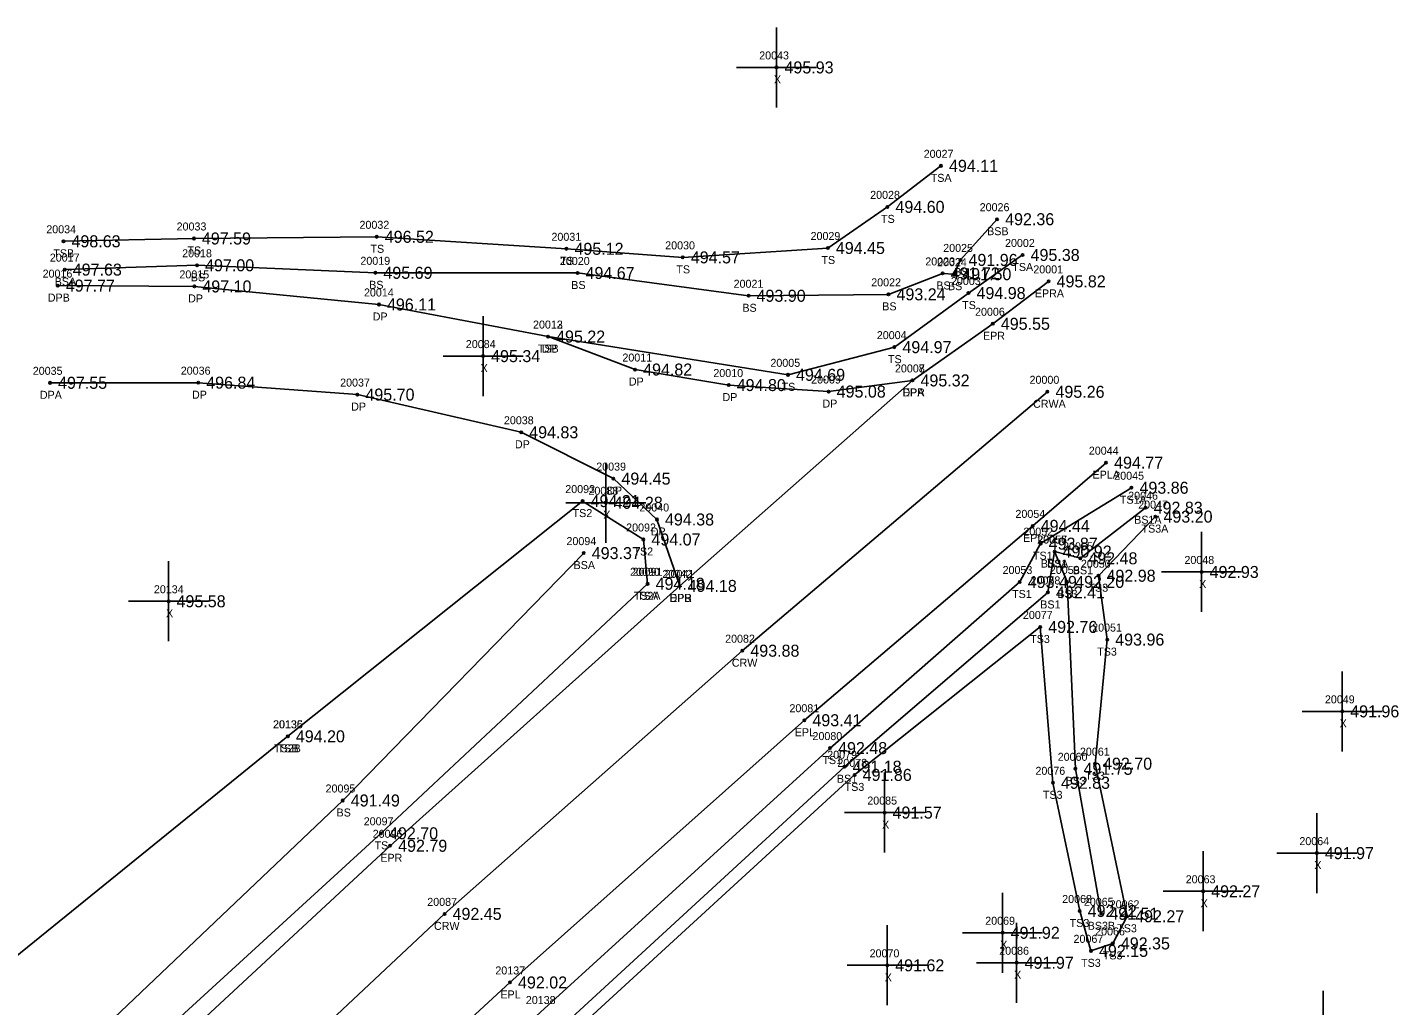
# Model space of a CAD drawing. Extents: x 1741010 to 1742139, y 749382 to 750625.
# Drawn here: x 1741967.6 to 1742139, y 750502.8 to 750625 of the extents above; entities that cross this region are included whole.
import ezdxf

# ---------------------------------------------------------------- set-up
doc = ezdxf.new("R2010")
doc.units = 0
for name, color, linetype in [('RD_DTM_BkLn1', 7, 'Continuous'), ('RD_DTM_BkLn2', 7, 'Continuous'), ('RD_DTM_BkLn_txCode', 7, 'Continuous'), ('RD_EX_Driveway', 7, 'Continuous'), ('RD_EX_Driveway_txCode', 7, 'Continuous'), ('RD_EX_Misc', 7, 'Continuous'), ('RD_EX_Misc_txCode', 7, 'Continuous'), ('RD_EX_Road', 7, 'Continuous'), ('RD_EX_Road_txCode', 7, 'Continuous'), ('RD_EX_TX_Driveway_ELEV', 7, 'Continuous'), ('RD_EX_TX_Misc_ELEV', 7, 'Continuous'), ('RD_EX_TX_Road_ELEV', 7, 'Continuous'), ('RD_HC_Survey_ELEV', 7, 'Continuous'), ('RD_HC_Survey_txCode', 7, 'Continuous'), ('RD_SMD_Locator', 7, 'Continuous')]:
    doc.layers.add(name, color=color, linetype=linetype)

msp = doc.modelspace()

# ---------------------------------------------------------------- linework, layer by layer
at = {"layer": 'RD_DTM_BkLn1'}
msp.add_lwpolyline([(1742095.1, 750579.47), (1742056.96, 750547.11), (1742019.74, 750514.22), (1741983.45, 750480.17), (1741948.01, 750445.01), (1741913.15, 750409.3), (1741879.03, 750372.99), (1741811.59, 750300.09), (1741743.65, 750226.52), (1741676.29, 750153.06), (1741642.32, 750115.53), (1741610.32, 750077.63)], dxfattribs=at)
at = {"layer": 'RD_DTM_BkLn2'}
for points in [[(1742081.79, 750607.71), (1742075.1, 750602.58), (1742067.65, 750597.44), (1742049.52, 750596.27), (1742034.98, 750597.34), (1742011.27, 750598.84), (1741988.41, 750598.63), (1741972.11, 750598.28)], [(1741972.27, 750594.74), (1741988.81, 750595.28), (1742011.1, 750594.34), (1742036.36, 750594.32), (1742057.74, 750591.47), (1742075.23, 750591.65), (1742081.99, 750594.26), (1742083.45, 750594.17), (1742084.23, 750595.95), (1742088.81, 750601.04)], [(1742091.99, 750596.57), (1742085.23, 750591.81), (1742075.97, 750585.05), (1742062.67, 750581.59), (1742032.68, 750586.37)], [(1742105.6, 750567.48), (1742094.25, 750560.49), (1742091.64, 750555.7), (1742067.93, 750534.94), (1742031.73, 750501.95), (1741994.85, 750467.63), (1741959.82, 750432.06), (1741925.8, 750396.31), (1741891.25, 750362.62), (1741824.36, 750287.7), (1741756.44, 750214.6), (1741688.69, 750142.04), (1741655.55, 750103.43), (1741644.64, 750083.31), (1741626.06, 750060.3), (1741620, 750055.3), (1741614.97, 750059.12), (1741617.5, 750064.27), (1741619.23, 750067.96)], [(1742107.37, 750564.98), (1742099.21, 750558.66), (1742095.99, 750559.5), (1742095.15, 750554.39), (1742069.73, 750532.61), (1742034.06, 750499.81), (1741997.6, 750464.99), (1741961.88, 750429.54), (1741928.13, 750394.17), (1741895.34, 750359.02), (1741826.5, 750286.36), (1741758.73, 750213.29), (1741690.1, 750140.59), (1741658.36, 750099.77), (1741650.43, 750077.87), (1741632.9, 750061.59), (1741621.97, 750051.56), (1741618.99, 750048.78), (1741611.88, 750047.79)], [(1742045.12, 750555.47), (1742044.6, 750561.01), (1742036.99, 750565.81), (1742000.15, 750536.41)], [(1742108.6, 750563.87), (1742101.48, 750556.48), (1742102.57, 750548.5), (1742101.05, 750532.99), (1742105.06, 750513.92), (1742103.27, 750510.53), (1742100.54, 750509.6), (1742099.13, 750514.58), (1742095.78, 750530.6), (1742094.19, 750550.08), (1742071, 750531.59), (1742035.26, 750498.87), (1741998.91, 750463.73), (1741964.71, 750427.12), (1741930.26, 750392.09), (1741896.36, 750357.96), (1741828.15, 750284.74), (1741760.22, 750211.9), (1741691.37, 750138.81), (1741661.95, 750096.11), (1741655.14, 750072.69), (1741637.21, 750056.01), (1741627.61, 750046.43), (1741623.09, 750045.5)], [(1742095.99, 750559.5), (1742097.56, 750555.71), (1742098.6, 750532.35), (1742101.83, 750514.23)], [(1742037.14, 750559.31), (1742007.02, 750528.39), (1741970.04, 750493.22), (1741934.59, 750458.38), (1741921.36, 750445.71), (1741908.08, 750432.71)], [(1742045.12, 750555.47), (1742011.8, 750524.29), (1741973.5, 750489.25), (1741973.31, 750490.05), (1741936.72, 750456.96), (1741909.62, 750428.48), (1741903.95, 750430.57), (1741885.98, 750437.55), (1741892.83, 750449.28), (1741921.95, 750473.14), (1741959.65, 750503.64), (1742000.15, 750536.41)]]:
    msp.add_lwpolyline(points, dxfattribs=at)
at = {"layer": 'RD_EX_Driveway'}
for points in [[(1742078.23, 750580.89), (1742067.75, 750579.5), (1742055.26, 750580.31), (1742043.56, 750582.25), (1742032.68, 750586.37), (1742011.54, 750590.38), (1741988.47, 750592.64), (1741971.4, 750592.74)], [(1741970.43, 750580.59), (1741988.95, 750580.61), (1742008.85, 750579.12), (1742029.32, 750574.41), (1742040.85, 750568.62), (1742046.29, 750563.51), (1742049.13, 750555.21)]]:
    msp.add_lwpolyline(points, dxfattribs=at)
at = {"layer": 'RD_EX_Misc'}
for p, q in [((1742061.23, 750615.01), (1742061.23, 750625.01)), ((1742056.23, 750620.01), (1742066.23, 750620.01)), ((1742024.56, 750578.93), (1742024.56, 750588.93)), ((1742019.56, 750583.93), (1742029.56, 750583.93)), ((1742039.88, 750560.6), (1742039.88, 750570.6)), ((1742034.88, 750565.6), (1742044.88, 750565.6)), ((1742114.37, 750551.95), (1742114.37, 750561.95)), ((1741985.24, 750548.29), (1741985.24, 750558.29)), ((1742109.37, 750556.95), (1742119.37, 750556.95)), ((1741980.24, 750553.29), (1741990.24, 750553.29)), ((1742131.94, 750534.53), (1742131.94, 750544.53)), ((1742126.94, 750539.53), (1742136.94, 750539.53)), ((1742074.74, 750521.88), (1742074.74, 750531.88)), ((1742069.74, 750526.88), (1742079.74, 750526.88)), ((1742128.77, 750516.81), (1742128.77, 750526.81)), ((1742114.56, 750512.04), (1742114.56, 750522.04)), ((1742123.77, 750521.81), (1742133.77, 750521.81)), ((1742089.5, 750506.86), (1742089.5, 750516.86)), ((1742109.56, 750517.04), (1742119.56, 750517.04)), ((1742075.07, 750502.79), (1742075.07, 750512.79)), ((1742084.5, 750511.86), (1742094.5, 750511.86)), ((1742091.25, 750503.11), (1742091.25, 750513.11)), ((1742086.25, 750508.11), (1742096.25, 750508.11)), ((1742070.07, 750507.79), (1742080.07, 750507.79)), ((1742129.55, 750494.61), (1742129.55, 750504.61))]:
    msp.add_line(p, q, dxfattribs=at)
at = {"layer": 'RD_EX_Road'}
for points in [[(1742095.24, 750593.27), (1742088.27, 750587.97), (1742078.23, 750580.89), (1742049.13, 750555.21), (1742012.94, 750522.73), (1741975.54, 750488.03), (1741940.71, 750452.82), (1741916.22, 750428.67), (1741904.72, 750416.99), (1741884.38, 750395.02), (1741870.75, 750380.27), (1741817.36, 750322.98), (1741803.89, 750307.66), (1741783.86, 750287.33), (1741735.44, 750234.07), (1741718.84, 750214.98), (1741710.25, 750205.58), (1741668.97, 750159.8), (1741635, 750122.49), (1741604.35, 750087.7), (1741600.63, 750085.47)], [(1742102.43, 750570.61), (1742093.26, 750562.71), (1742064.72, 750538.42), (1742027.92, 750505.65), (1741991.25, 750471.83), (1741956.32, 750436.98), (1741921.43, 750401.39), (1741886.79, 750364.93), (1741819.64, 750292.67), (1741751.78, 750219.01), (1741684.42, 750145.59), (1741650.98, 750108.5), (1741637.17, 750092.42), (1741621.17, 750073.94), (1741621.31, 750072.22), (1741619.24, 750070.27)]]:
    msp.add_lwpolyline(points, dxfattribs=at)
at = {"layer": 'RD_SMD_Locator'}
for centre in [(1742061.23, 750620.01), (1742081.79, 750607.71), (1742075.1, 750602.58), (1742088.81, 750601.04), (1742011.27, 750598.84), (1741972.11, 750598.28), (1741988.41, 750598.63), (1742034.98, 750597.34), (1742067.65, 750597.44), (1741988.81, 750595.28), (1742049.52, 750596.27), (1742084.23, 750595.95), (1742091.99, 750596.57), (1741972.27, 750594.74), (1742011.1, 750594.34), (1742036.36, 750594.32), (1742081.99, 750594.26), (1742083.45, 750594.17), (1741971.4, 750592.74), (1741988.47, 750592.64), (1742095.24, 750593.27), (1742011.54, 750590.38), (1742057.74, 750591.47), (1742075.23, 750591.65), (1742085.23, 750591.81), (1742088.27, 750587.97), (1742032.68, 750586.37), (1742032.68, 750586.37), (1742075.97, 750585.05), (1742024.56, 750583.93), (1742043.56, 750582.25), (1742062.67, 750581.59), (1741970.43, 750580.59), (1741988.95, 750580.61), (1742055.26, 750580.31), (1742078.23, 750580.89), (1742078.23, 750580.89), (1742008.85, 750579.12), (1742067.75, 750579.5), (1742095.1, 750579.47), (1742029.32, 750574.41), (1742102.43, 750570.61), (1742040.85, 750568.62), (1742105.6, 750567.48), (1742036.99, 750565.81), (1742039.88, 750565.6), (1742107.37, 750564.98), (1742046.29, 750563.51), (1742093.26, 750562.71), (1742108.6, 750563.87), (1742044.6, 750561.01), (1742037.14, 750559.31), (1742094.25, 750560.49), (1742095.99, 750559.5), (1742095.99, 750559.5), (1742099.21, 750558.66), (1742101.48, 750556.48), (1742114.37, 750556.95), (1742045.12, 750555.47), (1742045.12, 750555.47), (1742049.13, 750555.21), (1742049.13, 750555.21), (1742091.64, 750555.7), (1742095.15, 750554.39), (1742097.56, 750555.71), (1741985.24, 750553.29), (1742094.19, 750550.08), (1742102.57, 750548.5), (1742056.96, 750547.11), (1742131.94, 750539.53), (1742064.72, 750538.42), (1742000.15, 750536.41), (1742000.15, 750536.41), (1742067.93, 750534.94), (1742069.73, 750532.61), (1742098.6, 750532.35), (1742101.05, 750532.99), (1742071, 750531.59), (1742095.78, 750530.6), (1742007.02, 750528.39), (1742074.74, 750526.88), (1742011.8, 750524.29), (1742012.94, 750522.73), (1742128.77, 750521.81), (1742114.56, 750517.04), (1742019.74, 750514.22), (1742099.13, 750514.58), (1742101.83, 750514.23), (1742105.06, 750513.92), (1742089.5, 750511.86), (1742100.54, 750509.6), (1742103.27, 750510.53), (1742091.25, 750508.11), (1742075.07, 750507.79), (1742027.92, 750505.65)]:
    msp.add_circle(centre, 0.15, dxfattribs=at)

# ---------------------------------------------------------------- texts
at = {"layer": 'RD_DTM_BkLn_txCode'}
for s, p in [('20027', (1742079.63, 750608.71)), ('TSA', (1742080.51, 750605.71)), ('20028', (1742072.94, 750603.58)), ('20026', (1742086.63, 750602.04)), ('20033', (1741986.25, 750599.63)), ('20032', (1742009.11, 750599.84)), ('TS', (1742074.3, 750600.58)), ('20034', (1741969.96, 750599.28)), ('20031', (1742033.1, 750598.34)), ('20029', (1742065.49, 750598.44)), ('BSB', (1742087.56, 750599.04)), ('TSB', (1741970.84, 750596.28)), ('20018', (1741986.94, 750596.28)), ('TS', (1741987.61, 750596.63)), ('TS', (1742010.48, 750596.84)), ('20030', (1742047.32, 750597.27)), ('20025', (1742082.07, 750596.95)), ('20002', (1742089.8, 750597.57)), ('20017', (1741970.4, 750595.74)), ('20019', (1742009.22, 750595.34)), ('TS', (1742034.18, 750595.34)), ('20020', (1742034.16, 750595.32)), ('TS', (1742066.85, 750595.44)), ('20023', (1742079.83, 750595.26)), ('20024', (1742081.3, 750595.17)), ('TSA', (1742090.71, 750594.57)), ('BSA', (1741971.01, 750592.74)), ('BS', (1741988.03, 750593.28)), ('TS', (1742048.72, 750594.27)), ('20003', (1742083.04, 750592.81)), ('BS', (1742083.45, 750593.95)), ('BS', (1742010.32, 750592.34)), ('BS', (1742035.58, 750592.32)), ('20021', (1742055.87, 750592.47)), ('20022', (1742073.07, 750592.65)), ('BS', (1742081.21, 750592.26)), ('BS', (1742082.67, 750592.17)), ('BS', (1742056.97, 750589.47)), ('BS', (1742074.45, 750589.65)), ('TS', (1742084.44, 750589.81)), ('20013', (1742030.8, 750587.37)), ('20004', (1742073.77, 750586.05)), ('TSB', (1742031.41, 750584.37)), ('20005', (1742060.47, 750582.59)), ('TS', (1742075.17, 750583.05)), ('TS', (1742061.87, 750579.59)), ('20045', (1742103.45, 750568.48)), ('20093', (1742034.83, 750566.81)), ('TS1A', (1742104.15, 750565.48)), ('20046', (1742105.19, 750565.98)), ('TS2', (1742035.75, 750563.81)), ('20047', (1742106.44, 750564.87)), ('20092', (1742042.44, 750562.01)), ('BS1A', (1742105.94, 750562.98)), ('TS3A', (1742106.86, 750561.87)), ('20094', (1742034.98, 750560.31)), ('20052', (1742092.09, 750561.49)), ('20056', (1742093.81, 750560.5)), ('20057', (1742093.84, 750560.5)), ('TS2', (1742043.35, 750559.01)), ('TS1', (1742093.29, 750558.49)), ('20055', (1742097.05, 750559.66)), ('BSA', (1742035.87, 750557.31)), ('20053', (1742089.49, 750556.7)), ('BS3A', (1742094.28, 750557.5)), ('BS1', (1742095.05, 750557.5)), ('20059', (1742095.4, 750556.71)), ('20050', (1742099.28, 750557.48)), ('20090', (1742042.92, 750556.47)), ('20091', (1742043.25, 750556.47)), ('20058', (1742092.99, 750555.39)), ('BS1', (1742098.27, 750556.66)), ('TS2A', (1742043.39, 750553.47)), ('TSA', (1742043.84, 750553.47)), ('TS1', (1742090.68, 750553.7)), ('BS3', (1742096.33, 750553.71)), ('TS3', (1742100.23, 750554.48)), ('BS1', (1742094.2, 750552.39)), ('20077', (1742092.03, 750551.08)), ('20051', (1742100.69, 750549.5)), ('TS3', (1742092.94, 750548.08)), ('TS3', (1742101.32, 750546.5)), ('20136', (1741998.29, 750537.41)), ('20135', (1741998.32, 750537.41)), ('20080', (1742065.73, 750535.94)), ('TS2B', (1741998.43, 750534.41)), ('TSB', (1741998.88, 750534.41)), ('TS1', (1742066.97, 750532.94)), ('20079', (1742067.57, 750533.61)), ('20060', (1742096.38, 750533.35)), ('20061', (1742099.16, 750533.99)), ('20078', (1742068.84, 750532.59)), ('20076', (1742093.6, 750531.6)), ('20095', (1742004.87, 750529.39)), ('BS1', (1742068.78, 750530.61)), ('TS3', (1742069.75, 750529.59)), ('BS3', (1742097.37, 750530.35)), ('TS3', (1742099.81, 750530.99)), ('TS3', (1742094.53, 750528.6)), ('BS', (1742006.24, 750526.39)), ('20097', (1742009.64, 750525.29)), ('TS', (1742011, 750522.29)), ('20068', (1742096.94, 750515.58)), ('20065', (1742099.65, 750515.23)), ('20062', (1742102.88, 750514.92)), ('TS3', (1742097.88, 750512.58)), ('BS3B', (1742100.13, 750512.23)), ('20067', (1742098.36, 750510.6)), ('20066', (1742101.06, 750511.53)), ('TS3', (1742103.82, 750511.92)), ('TS3', (1742099.3, 750507.6)), ('TS3', (1742102.02, 750508.53)), ('20138', (1742029.9, 750502.95))]:
    msp.add_text(s, height=1, dxfattribs=at).set_placement(p)
at = {"layer": 'RD_EX_Driveway_txCode'}
for s, p in [('20016', (1741969.5, 750593.74)), ('20015', (1741986.6, 750593.64)), ('20014', (1742009.67, 750591.38)), ('DPB', (1741970.15, 750590.74)), ('DP', (1741987.69, 750590.64)), ('DP', (1742010.76, 750588.38)), ('20012', (1742030.8, 750587.37)), ('DP', (1742031.9, 750584.37)), ('20011', (1742041.97, 750583.25)), ('20035', (1741968.27, 750581.59)), ('20036', (1741986.77, 750581.61)), ('20010', (1742053.34, 750581.31)), ('20008', (1742076.04, 750581.89)), ('20037', (1742006.69, 750580.12)), ('DP', (1742042.78, 750580.25)), ('20009', (1742065.56, 750580.5)), ('DPA', (1741969.16, 750578.59)), ('DP', (1741988.17, 750578.61)), ('DP', (1742054.48, 750578.31)), ('DP', (1742066.97, 750577.5)), ('DPA', (1742076.97, 750578.89)), ('DP', (1742008.07, 750577.12)), ('20038', (1742027.16, 750575.41)), ('DP', (1742028.54, 750572.41)), ('20039', (1742038.7, 750569.62)), ('DP', (1742040.07, 750566.62)), ('20040', (1742044.09, 750564.51)), ('DP', (1742045.51, 750561.51)), ('20041', (1742047.25, 750556.21)), ('DPB', (1742047.87, 750553.21))]:
    msp.add_text(s, height=1, dxfattribs=at).set_placement(p)
at = {"layer": 'RD_EX_Misc_txCode'}
for s, p in [('20043', (1742059.07, 750621.01)), ('X', (1742060.91, 750618.01)), ('20084', (1742022.4, 750584.93)), ('X', (1742024.25, 750581.93)), ('20083', (1742037.73, 750566.6)), ('X', (1742039.57, 750563.6)), ('20048', (1742112.22, 750557.95)), ('20134', (1741983.41, 750554.29)), ('X', (1742114.06, 750554.95)), ('X', (1741984.93, 750551.29)), ('20049', (1742129.78, 750540.53)), ('X', (1742131.62, 750537.53)), ('20085', (1742072.58, 750527.88)), ('X', (1742074.43, 750524.88)), ('20064', (1742126.59, 750522.81)), ('X', (1742128.46, 750519.81)), ('20063', (1742112.38, 750518.04)), ('X', (1742114.24, 750515.04)), ('20069', (1742087.32, 750512.86)), ('20070', (1742072.87, 750508.79)), ('20086', (1742089.07, 750509.11)), ('X', (1742089.19, 750509.86)), ('X', (1742074.76, 750505.79)), ('X', (1742090.93, 750506.11))]:
    msp.add_text(s, height=1, dxfattribs=at).set_placement(p)
at = {"layer": 'RD_EX_Road_txCode'}
for s, p in [('20001', (1742093.33, 750594.27)), ('EPRA', (1742093.52, 750591.27)), ('20006', (1742086.05, 750588.97)), ('EPR', (1742087.04, 750585.97)), ('20007', (1742076.04, 750581.89)), ('EPR', (1742077.01, 750578.89)), ('20044', (1742100.27, 750571.61)), ('EPLA', (1742100.73, 750568.61)), ('20054', (1742091.1, 750563.71)), ('EPL', (1742092.06, 750560.71)), ('20042', (1742046.97, 750556.21)), ('EPR', (1742047.9, 750553.21)), ('20081', (1742062.85, 750539.42)), ('EPL', (1742063.52, 750536.42)), ('20096', (1742010.76, 750523.73)), ('EPR', (1742011.71, 750520.73)), ('20137', (1742026.09, 750506.65)), ('EPL', (1742026.72, 750503.65))]:
    msp.add_text(s, height=1, dxfattribs=at).set_placement(p)
at = {"layer": 'RD_EX_TX_Driveway_ELEV'}
for s, p in [('497.77', (1741972.4, 750591.99)), ('497.10', (1741989.47, 750591.89)), ('496.11', (1742012.54, 750589.63)), ('495.22', (1742033.68, 750585.62)), ('494.82', (1742044.56, 750581.5)), ('497.55', (1741971.43, 750579.84)), ('496.84', (1741989.95, 750579.86)), ('494.80', (1742056.26, 750579.56)), ('495.08', (1742068.75, 750578.75)), ('495.32', (1742079.23, 750580.14)), ('495.70', (1742009.85, 750578.37)), ('494.83', (1742030.32, 750573.66)), ('494.45', (1742041.85, 750567.87)), ('494.38', (1742047.29, 750562.76)), ('494.18', (1742050.13, 750554.46))]:
    msp.add_text(s, height=1.5, dxfattribs=at).set_placement(p)
at = {"layer": 'RD_EX_TX_Misc_ELEV'}
for s, p in [('495.93', (1742062.23, 750619.26)), ('494.11', (1742082.79, 750606.96)), ('494.60', (1742076.1, 750601.83)), ('492.36', (1742089.81, 750600.29)), ('498.63', (1741973.11, 750597.53)), ('497.59', (1741989.41, 750597.88)), ('496.52', (1742012.27, 750598.09)), ('495.12', (1742035.98, 750596.59)), ('494.45', (1742068.65, 750596.69)), ('495.38', (1742092.99, 750595.82)), ('497.63', (1741973.27, 750593.99)), ('497.00', (1741989.81, 750594.53)), ('494.57', (1742050.52, 750595.52)), ('491.96', (1742085.23, 750595.2)), ('495.69', (1742012.1, 750593.59)), ('494.67', (1742037.36, 750593.57)), ('491.72', (1742082.99, 750593.51)), ('491.50', (1742084.45, 750593.42)), ('493.90', (1742058.74, 750590.72)), ('493.24', (1742076.23, 750590.9)), ('494.98', (1742086.23, 750591.06)), ('495.22', (1742033.68, 750585.62)), ('494.97', (1742076.97, 750584.3)), ('495.34', (1742025.56, 750583.18)), ('494.69', (1742063.67, 750580.84)), ('493.86', (1742106.6, 750566.73)), ('494.21', (1742037.99, 750565.06)), ('494.28', (1742040.88, 750564.85)), ('492.83', (1742108.37, 750564.23)), ('493.20', (1742109.6, 750563.12)), ('494.07', (1742045.6, 750560.26)), ('493.87', (1742095.25, 750559.74)), ('493.37', (1742038.14, 750558.56)), ('490.92', (1742096.99, 750558.75)), ('490.92', (1742096.99, 750558.75)), ('492.48', (1742100.21, 750557.91)), ('492.93', (1742115.37, 750556.2)), ('494.18', (1742046.12, 750554.72)), ('494.18', (1742046.12, 750554.72)), ('493.49', (1742092.64, 750554.95)), ('492.20', (1742098.56, 750554.96)), ('492.98', (1742102.48, 750555.73)), ('492.41', (1742096.15, 750553.64)), ('495.58', (1741986.24, 750552.54)), ('492.76', (1742095.19, 750549.33)), ('493.96', (1742103.57, 750547.75)), ('491.96', (1742132.94, 750538.78)), ('494.20', (1742001.15, 750535.66)), ('494.20', (1742001.15, 750535.66)), ('492.48', (1742068.93, 750534.19)), ('492.70', (1742102.05, 750532.24)), ('491.18', (1742070.73, 750531.86)), ('491.86', (1742072, 750530.84)), ('491.75', (1742099.6, 750531.6)), ('492.83', (1742096.78, 750529.85)), ('491.49', (1742008.02, 750527.64)), ('491.57', (1742075.74, 750526.13)), ('492.70', (1742012.8, 750523.54)), ('491.97', (1742129.77, 750521.06)), ('492.27', (1742115.56, 750516.29)), ('492.22', (1742100.13, 750513.83)), ('491.51', (1742102.83, 750513.48)), ('492.27', (1742106.06, 750513.17)), ('491.92', (1742090.5, 750511.11)), ('492.15', (1742101.54, 750508.85)), ('492.35', (1742104.27, 750509.78)), ('491.62', (1742076.07, 750507.04)), ('491.97', (1742092.25, 750507.36))]:
    msp.add_text(s, height=1.5, dxfattribs=at).set_placement(p)
at = {"layer": 'RD_EX_TX_Road_ELEV'}
for s, p in [('495.82', (1742096.24, 750592.52)), ('495.55', (1742089.27, 750587.22)), ('495.32', (1742079.23, 750580.14)), ('494.77', (1742103.43, 750569.86)), ('494.44', (1742094.26, 750561.96)), ('494.18', (1742050.13, 750554.46)), ('493.41', (1742065.72, 750537.67)), ('492.79', (1742013.94, 750521.98)), ('492.02', (1742028.92, 750504.9))]:
    msp.add_text(s, height=1.5, dxfattribs=at).set_placement(p)
at = {"layer": 'RD_HC_Survey_ELEV'}
for s, p in [('495.26', (1742096.1, 750578.72)), ('493.88', (1742057.96, 750546.36)), ('492.45', (1742020.74, 750513.47))]:
    msp.add_text(s, height=1.5, dxfattribs=at).set_placement(p)
at = {"layer": 'RD_HC_Survey_txCode'}
for s, p in [('20000', (1742092.86, 750580.47)), ('CRWA', (1742093.3, 750577.47)), ('20082', (1742054.81, 750548.11)), ('CRW', (1742055.65, 750545.11)), ('20087', (1742017.58, 750515.22)), ('CRW', (1742018.42, 750512.22))]:
    msp.add_text(s, height=1, dxfattribs=at).set_placement(p)

doc.saveas('drawing.dxf')
